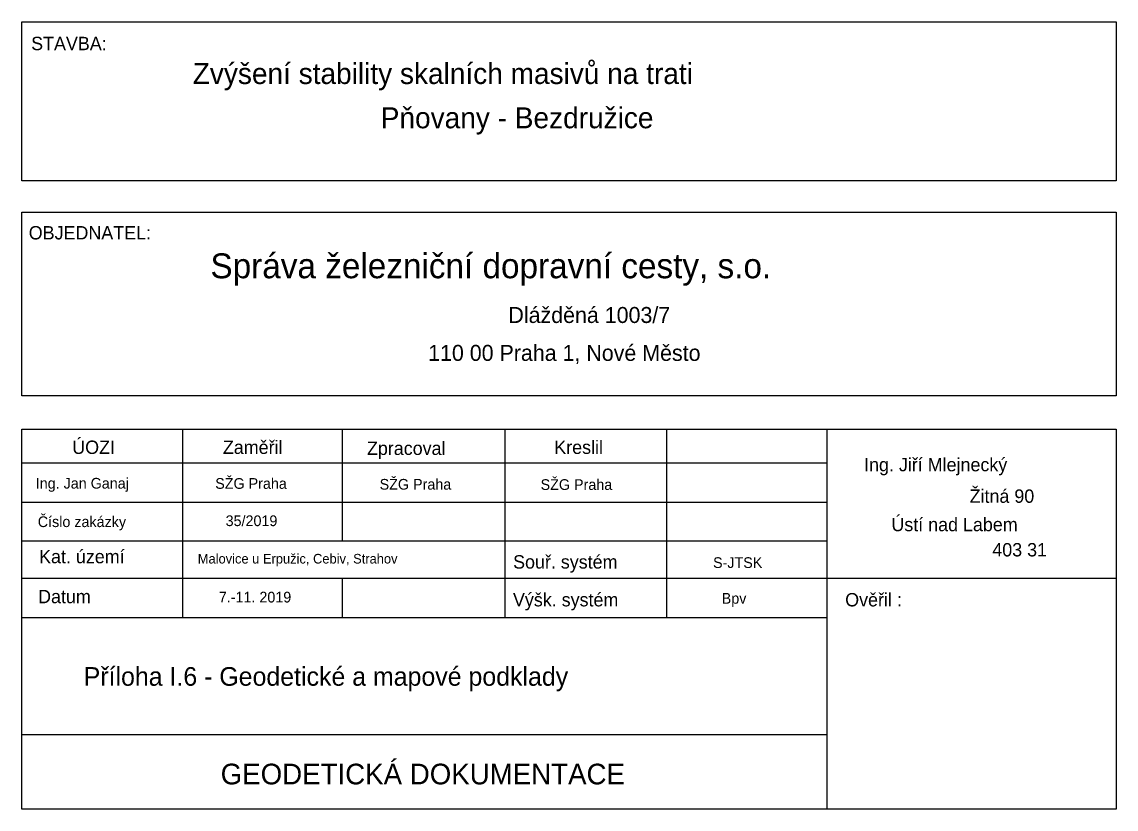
# Model space of a CAD drawing. Extents: x -879530 to -879371, y -1019242 to -1019127.
import ezdxf

# ---------------------------------------------------------------- set-up
doc = ezdxf.new("R2010")
doc.units = 0
doc.layers.add('LEGENDA', color=7, linetype='Continuous')
doc.layers.add('tabulka', color=7, linetype='Continuous')

msp = doc.modelspace()

# ---------------------------------------------------------------- linework, layer by layer
at = {"layer": 'tabulka'}
for p, q in [((-879530.09, -1019186.45), (-879371.44, -1019186.45)), ((-879506.8, -1019186.45), (-879506.8, -1019213.77)), ((-879483.66, -1019186.45), (-879483.66, -1019202.65)), ((-879460.06, -1019186.45), (-879460.06, -1019213.77)), ((-879436.61, -1019186.45), (-879436.61, -1019213.77)), ((-879413.31, -1019241.58), (-879413.31, -1019186.45)), ((-879530.09, -1019191.36), (-879413.31, -1019191.36)), ((-879530.09, -1019197.07), (-879413.31, -1019197.07)), ((-879530.09, -1019202.65), (-879413.31, -1019202.65)), ((-879530.09, -1019208.07), (-879371.44, -1019208.07)), ((-879483.66, -1019208.07), (-879483.66, -1019213.77)), ((-879530.09, -1019213.77), (-879413.31, -1019213.77)), ((-879530.09, -1019230.76), (-879413.31, -1019230.76))]:
    msp.add_line(p, q, dxfattribs=at)
for points in [[(-879530.09, -1019127.36), (-879371.44, -1019127.36), (-879371.44, -1019150.43), (-879530.09, -1019150.43)], [(-879530.09, -1019154.95), (-879371.44, -1019154.95), (-879371.44, -1019181.64), (-879530.09, -1019181.64)]]:
    msp.add_lwpolyline(points, close=True, dxfattribs=at)
msp.add_lwpolyline([(-879371.44, -1019186.45), (-879371.44, -1019241.58), (-879530.09, -1019241.58), (-879530.09, -1019186.45)], dxfattribs=at)

# ---------------------------------------------------------------- texts
at = {"layer": 'LEGENDA'}
for s, p in [('Zvýšení stability skalních masivů na trati', (-879505.32, -1019136.38)), ('Pňovany - Bezdružice', (-879478.06, -1019142.8))]:
    msp.add_text(s, height=3.04, dxfattribs=at).set_placement(p)
at = {"layer": 'tabulka'}
for s, height, p in [('STAVBA:', 1.94, (-879528.75, -1019131.47)), ('OBJEDNATEL:', 1.94, (-879529.1, -1019158.93)), ('Správa železniční dopravní cesty, s.o.', 3.61, (-879502.75, -1019164.56)), ('Dlážděná 1003/7', 2.32, (-879459.55, -1019171.05)), ('110 00 Praha 1, Nové Město', 2.32, (-879471.19, -1019176.55)), ('ÚOZI', 1.94, (-879522.79, -1019190.05)), ('Zaměřil', 1.94, (-879500.95, -1019190.05)), ('Zpracoval', 1.94, (-879480.06, -1019190.2)), ('Kreslil', 1.94, (-879452.9, -1019190.05)), ('Ing. Jiří Mlejnecký', 1.94, (-879407.98, -1019192.57)), ('Ing. Jan Ganaj', 1.552, (-879528.08, -1019195.08)), ('SŽG Praha', 1.552, (-879502.06, -1019195.11)), ('SŽG Praha', 1.552, (-879478.22, -1019195.23)), ('SŽG Praha', 1.552, (-879454.88, -1019195.27)), ('Žitná 90', 1.94, (-879392.68, -1019197.14)), ('Číslo zakázky', 1.552, (-879527.79, -1019200.66)), ('35/2019', 1.552, (-879500.55, -1019200.52)), ('Ústí nad Labem', 1.94, (-879404.02, -1019201.26)), ('403 31', 1.94, (-879389.39, -1019204.92)), ('Kat. území', 1.94, (-879527.6, -1019205.91)), ('Malovice u Erpužic, Cebiv, Strahov', 1.3968, (-879504.59, -1019205.95)), ('Souř. systém', 1.94, (-879458.87, -1019206.68)), ('S-JTSK', 1.552, (-879429.88, -1019206.59)), ('Datum', 1.94, (-879527.74, -1019211.71)), ('7.-11. 2019', 1.552, (-879501.54, -1019211.6)), ('Výšk. systém', 1.94, (-879458.89, -1019212.17)), ('Bpv', 1.552, (-879428.62, -1019211.78)), ('Ověřil :', 1.94, (-879410.72, -1019212.17)), ('Příloha I.6 - Geodetické a mapové podklady', 2.7, (-879521.13, -1019223.68)), ('GEODETICKÁ DOKUMENTACE ', 3, (-879501.27, -1019237.99))]:
    msp.add_text(s, height=height, dxfattribs=at).set_placement(p)

doc.saveas('drawing.dxf')
